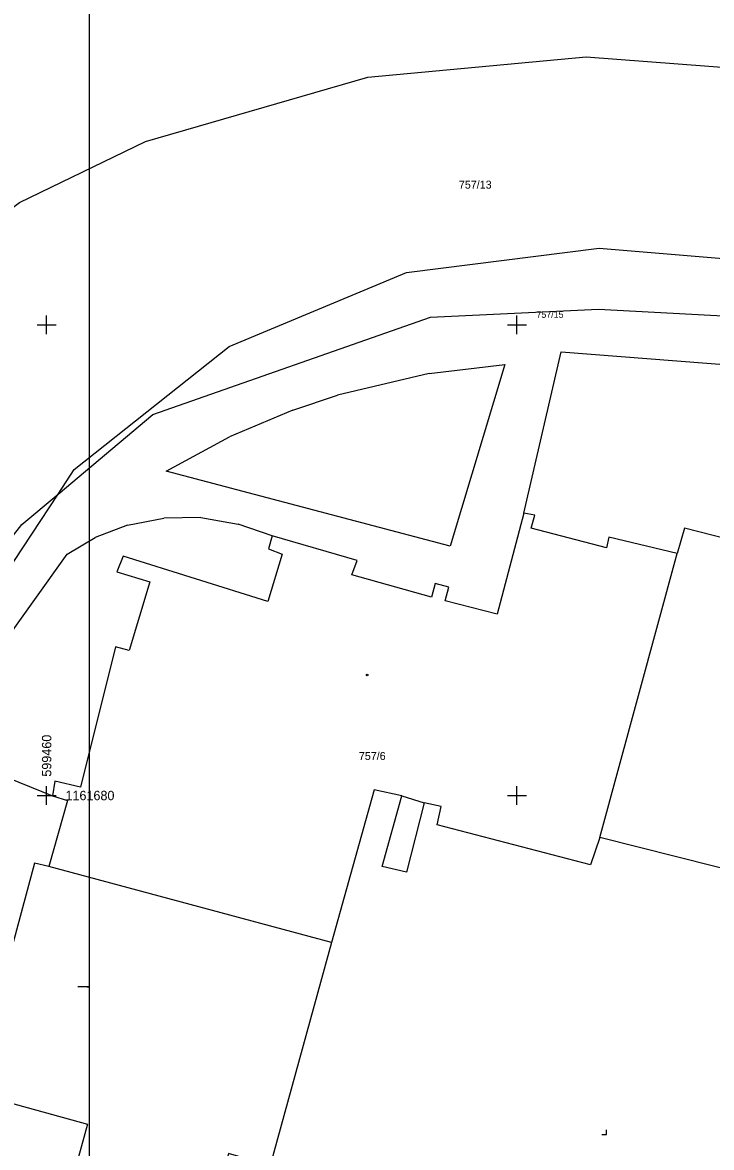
# Model space of a CAD drawing. Extents: x -599717 to -599336, y -1161826 to -1161587.
# Drawn here: x -599461.03 to -599431.73, y -1161694.96 to -1161647.15 of the extents above; entities that cross this region are included whole.
import ezdxf

# ---------------------------------------------------------------- set-up
doc = ezdxf.new("R2010")
doc.units = 0
for name, color, linetype in [('KN_Hranice parcel', 7, 'Continuous'), ('KN_Parcelní čísla', 7, 'Continuous'), ('KN_Vnitřní kresba', 7, 'Continuous'), ('KN_Značky budov', 7, 'Continuous'), ('KN_Značky kultur', 7, 'Continuous'), ('X_RAM_ROZPISKA', 7, 'Continuous'), ('X_SOUR_KRIZKY_SEVER', 7, 'Continuous')]:
    doc.layers.add(name, color=color, linetype=linetype)

msp = doc.modelspace()

# ---------------------------------------------------------------- linework, layer by layer
at = {"layer": 'KN_Hranice parcel'}
for p, q in [((-599436.48, -1161681.78), (-599433.19, -1161669.71)), ((-599447.89, -1161686.25), (-599459.91, -1161683.02))]:
    msp.add_line(p, q, dxfattribs=at)
for points in [[(-599472.61, -1161674.6), (-599466.59, -1161665.85), (-599464.35, -1161663.46), (-599461.66, -1161661.04), (-599464.98, -1161657.69), (-599461.15, -1161654.8), (-599455.8, -1161652.2), (-599446.34, -1161649.47), (-599437.06, -1161648.61), (-599425.51, -1161649.49), (-599419.92, -1161649.97)], [(-599459.51, -1161667.19), (-599458.83, -1161666.15), (-599452.24, -1161660.92), (-599444.7, -1161657.78), (-599436.51, -1161656.74), (-599424.44, -1161657.75)], [(-599459.51, -1161667.19), (-599455.48, -1161663.81), (-599443.68, -1161659.67), (-599436.53, -1161659.33), (-599421.97, -1161660.11), (-599409.32, -1161661.5)], [(-599482.07, -1161728.43), (-599482.2, -1161727.17), (-599480.67, -1161718.88), (-599478.61, -1161710.51), (-599472.1, -1161690.95), (-599466.87, -1161675.9), (-599461.06, -1161668.48), (-599459.51, -1161667.19)], [(-599482.07, -1161728.43), (-599464.01, -1161674), (-599459.51, -1161667.19)], [(-599433.19, -1161669.71), (-599436.1, -1161669.02), (-599436.2, -1161669.48), (-599439.4, -1161668.64), (-599439.24, -1161668.08), (-599439.71, -1161668), (-599440.84, -1161672.3), (-599443.05, -1161671.72), (-599442.9, -1161671.14), (-599443.48, -1161670.99), (-599443.63, -1161671.57), (-599447.02, -1161670.62), (-599446.79, -1161670.01), (-599450.41, -1161668.96), (-599450.57, -1161669.52), (-599449.99, -1161669.74), (-599450.59, -1161671.75), (-599456.74, -1161669.83), (-599457.01, -1161670.5), (-599455.61, -1161670.92), (-599456.49, -1161673.84), (-599457.07, -1161673.68), (-599458.56, -1161679.64), (-599459.65, -1161679.39), (-599459.75, -1161680.01), (-599459.12, -1161680.21), (-599459.91, -1161683.02)], [(-599417.3, -1161671.51), (-599420.44, -1161670.72), (-599420.65, -1161671.36), (-599423.02, -1161670.77), (-599422.85, -1161670.14), (-599423.63, -1161669.95), (-599425.05, -1161675.65), (-599427.46, -1161675.04), (-599426.29, -1161670.39), (-599426.77, -1161670.26), (-599426.92, -1161670.85), (-599430.01, -1161670.13), (-599429.89, -1161669.41), (-599432.88, -1161668.64), (-599433.19, -1161669.71)], [(-599436.48, -1161681.78), (-599436.87, -1161682.95), (-599443.4, -1161681.24), (-599443.23, -1161680.46), (-599443.94, -1161680.31), (-599444.7, -1161683.26), (-599445.74, -1161683.01), (-599444.89, -1161680.02), (-599446.07, -1161679.76), (-599447.89, -1161686.25)], [(-599420.5, -1161684.42), (-599420.68, -1161685.11), (-599427.06, -1161683.49), (-599426.88, -1161682.56), (-599429.57, -1161681.86), (-599429.95, -1161683.43), (-599436.48, -1161681.78)], [(-599459.91, -1161683.02), (-599460.52, -1161682.87), (-599462.22, -1161689.15), (-599461.64, -1161689.31), (-599462.42, -1161692.2), (-599463, -1161692.05), (-599463.16, -1161692.62), (-599458.26, -1161693.97), (-599458.92, -1161696.33), (-599464.95, -1161694.63), (-599465.17, -1161695.4), (-599464.59, -1161695.56), (-599465.27, -1161697.96), (-599465.85, -1161697.8), (-599466.8, -1161701.17)], [(-599447.89, -1161686.25), (-599450.49, -1161695.73), (-599452.27, -1161695.22), (-599452.89, -1161697.65), (-599452.18, -1161697.79), (-599454.12, -1161704.55)]]:
    msp.add_lwpolyline(points, dxfattribs=at)
at = {"layer": 'KN_Vnitřní kresba'}
for p, q in [((-599439.71, -1161668), (-599438.12, -1161661.14)), ((-599438.12, -1161661.14), (-599410.59, -1161663.28)), ((-599443.74, -1161662.06), (-599440.51, -1161661.68)), ((-599440.51, -1161661.68), (-599442.84, -1161669.41)), ((-599443.74, -1161662.06), (-599447.63, -1161662.98)), ((-599449.53, -1161663.62), (-599447.63, -1161662.98)), ((-599449.53, -1161663.62), (-599452.23, -1161664.76)), ((-599454.92, -1161666.22), (-599452.23, -1161664.76)), ((-599442.84, -1161669.41), (-599454.92, -1161666.22)), ((-599456.56, -1161668.51), (-599455.02, -1161668.21)), ((-599453.45, -1161668.18), (-599455.02, -1161668.21)), ((-599453.45, -1161668.18), (-599451.86, -1161668.47)), ((-599450.41, -1161668.96), (-599451.86, -1161668.47)), ((-599456.56, -1161668.51), (-599457.94, -1161669.04)), ((-599459.13, -1161669.74), (-599457.94, -1161669.04)), ((-599464.97, -1161677.92), (-599459.13, -1161669.74)), ((-599464.97, -1161677.92), (-599459.75, -1161680.01)), ((-599444.89, -1161680.02), (-599443.94, -1161680.31))]:
    msp.add_line(p, q, dxfattribs=at)
at = {"layer": 'KN_Značky budov'}
msp.add_circle((-599446.371, -1161674.88), 0.035, dxfattribs=at)
at = {"layer": 'KN_Značky kultur'}
for p, q in [((-599436.19, -1161694.41), (-599436.19, -1161694.21)), ((-599436.39, -1161694.41), (-599436.19, -1161694.41))]:
    msp.add_line(p, q, dxfattribs=at)
at = {"layer": 'X_RAM_ROZPISKA'}
for p, q in [((-599458.175, -1161688.135), (-599458.675, -1161688.135)), ((-599458.275, -1161688.135), (-599458.175, -1161688.135))]:
    msp.add_line(p, q, dxfattribs=at)
msp.add_lwpolyline([(-599584.175, -1161747.535), (-599458.175, -1161747.535), (-599458.175, -1161628.735), (-599584.175, -1161628.735)], close=True, dxfattribs=at)
at = {"layer": 'X_SOUR_KRIZKY_SEVER'}
for p, q in [((-599460, -1161660.4), (-599460, -1161659.6)), ((-599440, -1161660.4), (-599440, -1161659.6)), ((-599460.4, -1161660), (-599459.6, -1161660)), ((-599440.4, -1161660), (-599439.6, -1161660)), ((-599460, -1161680.4), (-599460, -1161679.6)), ((-599440, -1161680.4), (-599440, -1161679.6)), ((-599460.4, -1161680), (-599459.6, -1161680)), ((-599440.4, -1161680), (-599439.6, -1161680))]:
    msp.add_line(p, q, dxfattribs=at)

# ---------------------------------------------------------------- texts
at = {"layer": 'KN_Parcelní čísla'}
for s, height, p in [('757/13', 0.34, (-599442.47, -1161654.21)), ('757/15', 0.28, (-599439.17, -1161659.7)), ('757/6', 0.34, (-599446.723, -1161678.49))]:
    msp.add_text(s, height=height, dxfattribs=at).set_placement(p)
at = {"layer": 'X_SOUR_KRIZKY_SEVER'}
msp.add_text('599460', height=0.4, rotation=90, dxfattribs=at).set_placement((-599459.8, -1161679.2))
msp.add_text('1161680', height=0.4, dxfattribs=at).set_placement((-599459.2, -1161680.2))

doc.saveas('drawing.dxf')
